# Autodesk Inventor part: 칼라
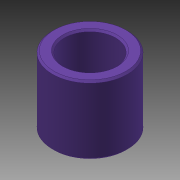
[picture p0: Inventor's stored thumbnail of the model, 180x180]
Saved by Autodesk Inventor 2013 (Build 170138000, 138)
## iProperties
Created: 2015-09
Part Number: 칼라
Document SubType Name: Modeling
Designer: mduedu
Density: 1 g/cm^3
Material: 스테인리스강
Author: mduedu
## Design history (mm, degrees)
node "작업 평면1"
node "작업 평면2"
sketch "스케치1"
  geometry: C1 r 7.5 at (0, 0); C2 r 11 at (0, 0); 1 further point
  constraints: 2 centre point, 2 coincident
  dimensions: "d0" = 15 diameter of C1; "d1" = 22 diameter of C2
extrude "돌출1" new body sketch "스케치1" distance "d2" = 20; taper "d3" = 0 deg
chamfer "모따기1" distance "d4" = 0.5; stored, may be unused: second distance "d5" = 2, angle "d6" = 45 deg
node "솔리드1"
